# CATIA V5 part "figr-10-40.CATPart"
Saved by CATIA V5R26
Part number: Part3
Bounding box of the stored display mesh (mm): x -57.458 to 20, y -85.932 to 127.979, z -59.826 to 86.386
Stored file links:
  D:\_Deepak\CATIA\CATIA V5 2015 Parts Files\Part files\Partfiles\c10_catia_v5_6r2015_prt\figr-10-37-1.CATPart
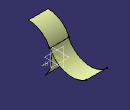
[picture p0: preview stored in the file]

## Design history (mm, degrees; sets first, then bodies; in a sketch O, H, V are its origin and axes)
Body1 (main body)
  Sketch1 on yz-plane, origin (0, 0, 0), H (0, 1, 0), V (0, 0, 1)
    arc A1 centre (-86.3872, 0) radius 86.3872 from (-24.0683, -59.8256) to (-85.9323, 86.386) ccw
    point P1 (-86.3872, 0)
    coincidence: A1 O, P1 H
  Extrude1: Lim1 20, Lim2 53, Element1 Sketch1
  Sketch2 on zx-plane, origin (0, 0, 0), H (-1, 0, 0), V (0, 0, 1)
    line L1 (-18.8028, 37.5161) -> (51.5353, 37.5161)
    horizontal: L1 H
  Project1: ToProject Sketch2, Support Extrude1
  Sketch3 on xy-plane, origin (0, 0, 0), H (1, 0, 0), V (0, 1, 0)
    line L1 (-57.4576, 127.9794) -> (17.5097, 127.9794)
    horizontal: L1 H
  Sweep1: type Circle, Guide (Project1; Sketch3), Reference Extrude1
